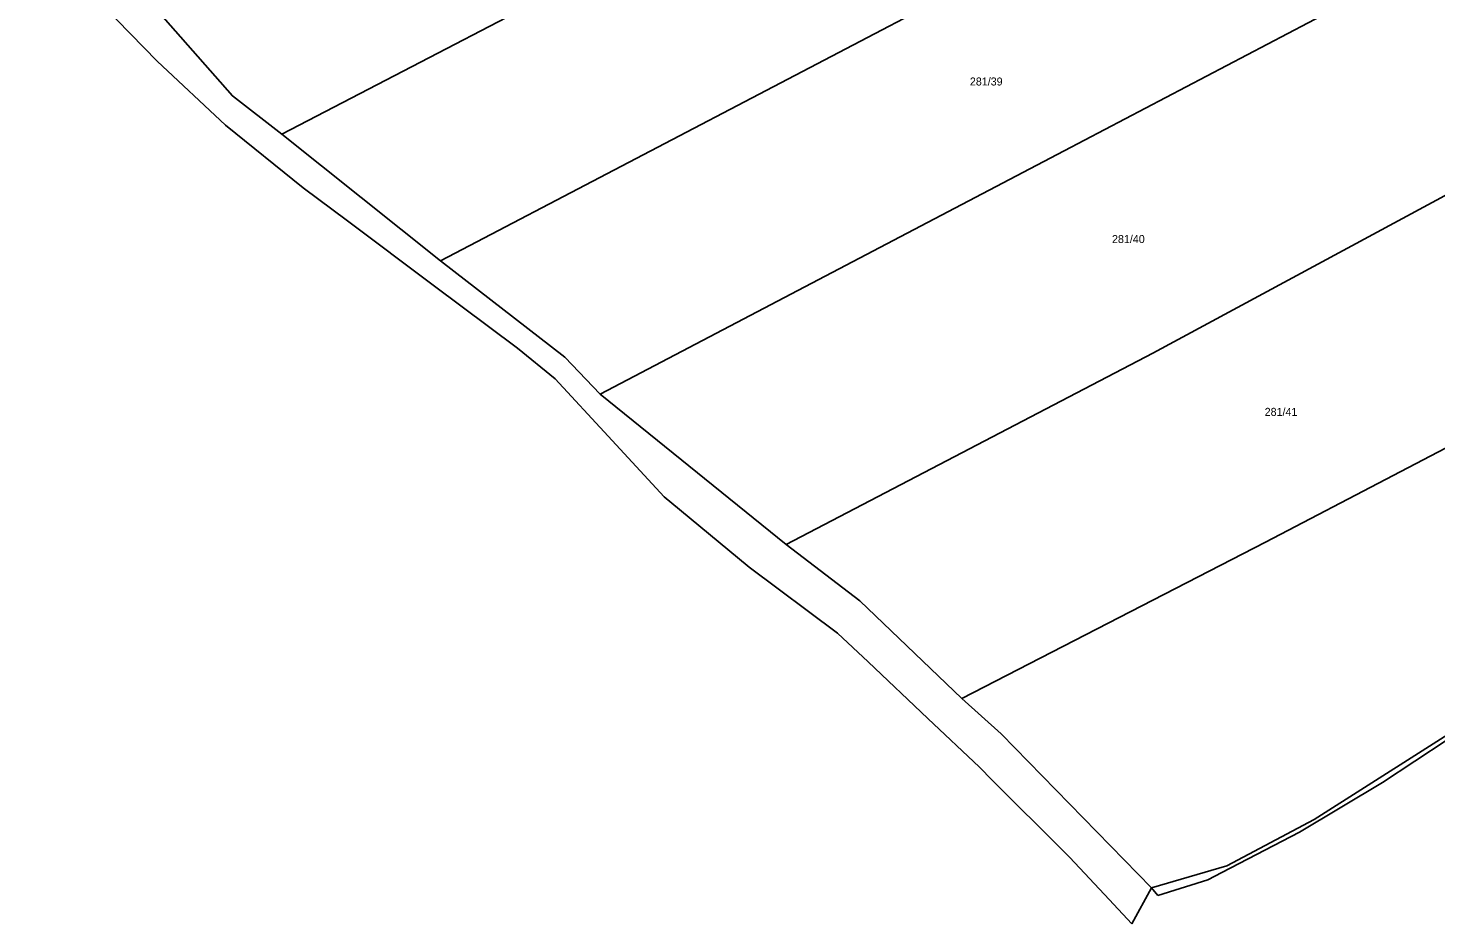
# Model space of a CAD drawing. Extents: x -779723 to -777378, y -1011169 to -1009297.
# Drawn here: x -778495.1 to -778196, y -1011158.6 to -1010968.2 of the extents above; entities that cross this region are included whole.
import ezdxf

# ---------------------------------------------------------------- set-up
doc = ezdxf.new("R2010")
doc.units = 0
doc.layers.add('Hranice parcel', color=7, linetype='Continuous')
doc.layers.add('Parcelní čísla', color=7, linetype='Continuous')

msp = doc.modelspace()

# ---------------------------------------------------------------- linework, layer by layer
at = {"layer": 'Hranice parcel'}
for p, q in [((-778407.53, -1011017.65), (-778441.21, -1010990.73)), ((-778436.69, -1011002.15), (-778427.3, -1011009.18)), ((-778427.3, -1011009.18), (-778409.1, -1011022.81)), ((-778409.1, -1011022.81), (-778391.18, -1011036.23)), ((-778391.18, -1011036.23), (-778383.16, -1011042.74)), ((-778334.09, -1011077.94), (-778373.57, -1011045.99)), ((-778360.01, -1011067.81), (-778356.76, -1011070.5)), ((-778323.17, -1011096.78), (-778316.68, -1011102.92)), ((-778316.68, -1011102.92), (-778303.94, -1011114.98)), ((-778273.83, -1011144.47), (-778265.43, -1011153.45)), ((-778256.47, -1011150.93), (-778260.61, -1011158.61)), ((-778255.11, -1011152.59), (-778256.47, -1011150.93)), ((-778265.43, -1011153.45), (-778260.61, -1011158.61))]:
    msp.add_line(p, q, dxfattribs=at)
for points in [[(-778441.21, -1010990.73), (-778362.13, -1010949.54), (-778217.88, -1010871.59)], [(-778407.53, -1011017.65), (-778253.66, -1010937.12), (-778197.62, -1010906.38)], [(-778373.57, -1011045.99), (-778274.98, -1010994.26), (-778175.63, -1010942.03)], [(-778495.13, -1010946.65), (-778490.52, -1010951.78), (-778467.75, -1010975.19)], [(-778441.21, -1010990.73), (-778451.73, -1010982.61), (-778468.57, -1010963.46)], [(-778467.75, -1010975.19), (-778453.23, -1010988.79), (-778436.69, -1011002.15)], [(-778334.09, -1011077.94), (-778256.2, -1011037.27), (-778150.99, -1010980.51)], [(-778373.57, -1011045.99), (-778381.12, -1011038.16), (-778407.53, -1011017.65)], [(-778296.77, -1011110.73), (-778232.23, -1011077.49), (-778123.71, -1011020.78)], [(-778383.16, -1011042.74), (-778371.88, -1011054.95), (-778360.01, -1011067.81)], [(-778100.49, -1011056.2), (-778110.44, -1011062.73), (-778164.52, -1011099.92), (-778221.91, -1011136.43), (-778240.47, -1011146.31), (-778256.47, -1011150.93)], [(-778356.76, -1011070.5), (-778341.95, -1011082.76), (-778323.17, -1011096.78)], [(-778296.77, -1011110.73), (-778318.44, -1011089.92), (-778334.09, -1011077.94)], [(-778256.47, -1011150.93), (-778288.36, -1011118.19), (-778296.77, -1011110.73)], [(-778303.94, -1011114.98), (-778293.02, -1011125.32), (-778290.3, -1011128.03)], [(-778186.77, -1011114.94), (-778207.39, -1011128.57), (-778224.98, -1011139.15), (-778241.5, -1011147.68)], [(-778290.3, -1011128.03), (-778274.99, -1011143.31), (-778273.83, -1011144.47)], [(-778241.5, -1011147.68), (-778244.49, -1011149.23), (-778255.11, -1011152.59)]]:
    msp.add_lwpolyline(points, dxfattribs=at)

# ---------------------------------------------------------------- texts
at = {"layer": 'Parcelní čísla'}
for s, p in [('281/39', (-778295.04, -1010980.39)), ('281/40', (-778264.84, -1011013.88)), ('281/41', (-778232.4, -1011050.62))]:
    msp.add_text(s, height=1.7, dxfattribs=at).set_placement(p)

doc.saveas('drawing.dxf')
